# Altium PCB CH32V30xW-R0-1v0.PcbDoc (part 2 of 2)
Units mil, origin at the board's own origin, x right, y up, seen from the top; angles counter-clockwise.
Board outline 3543.31 x 3070.87 mil, 2 copper layers (Top Layer, Bottom Layer); 66 components, 88 nets, 346 pads, 719 vias.
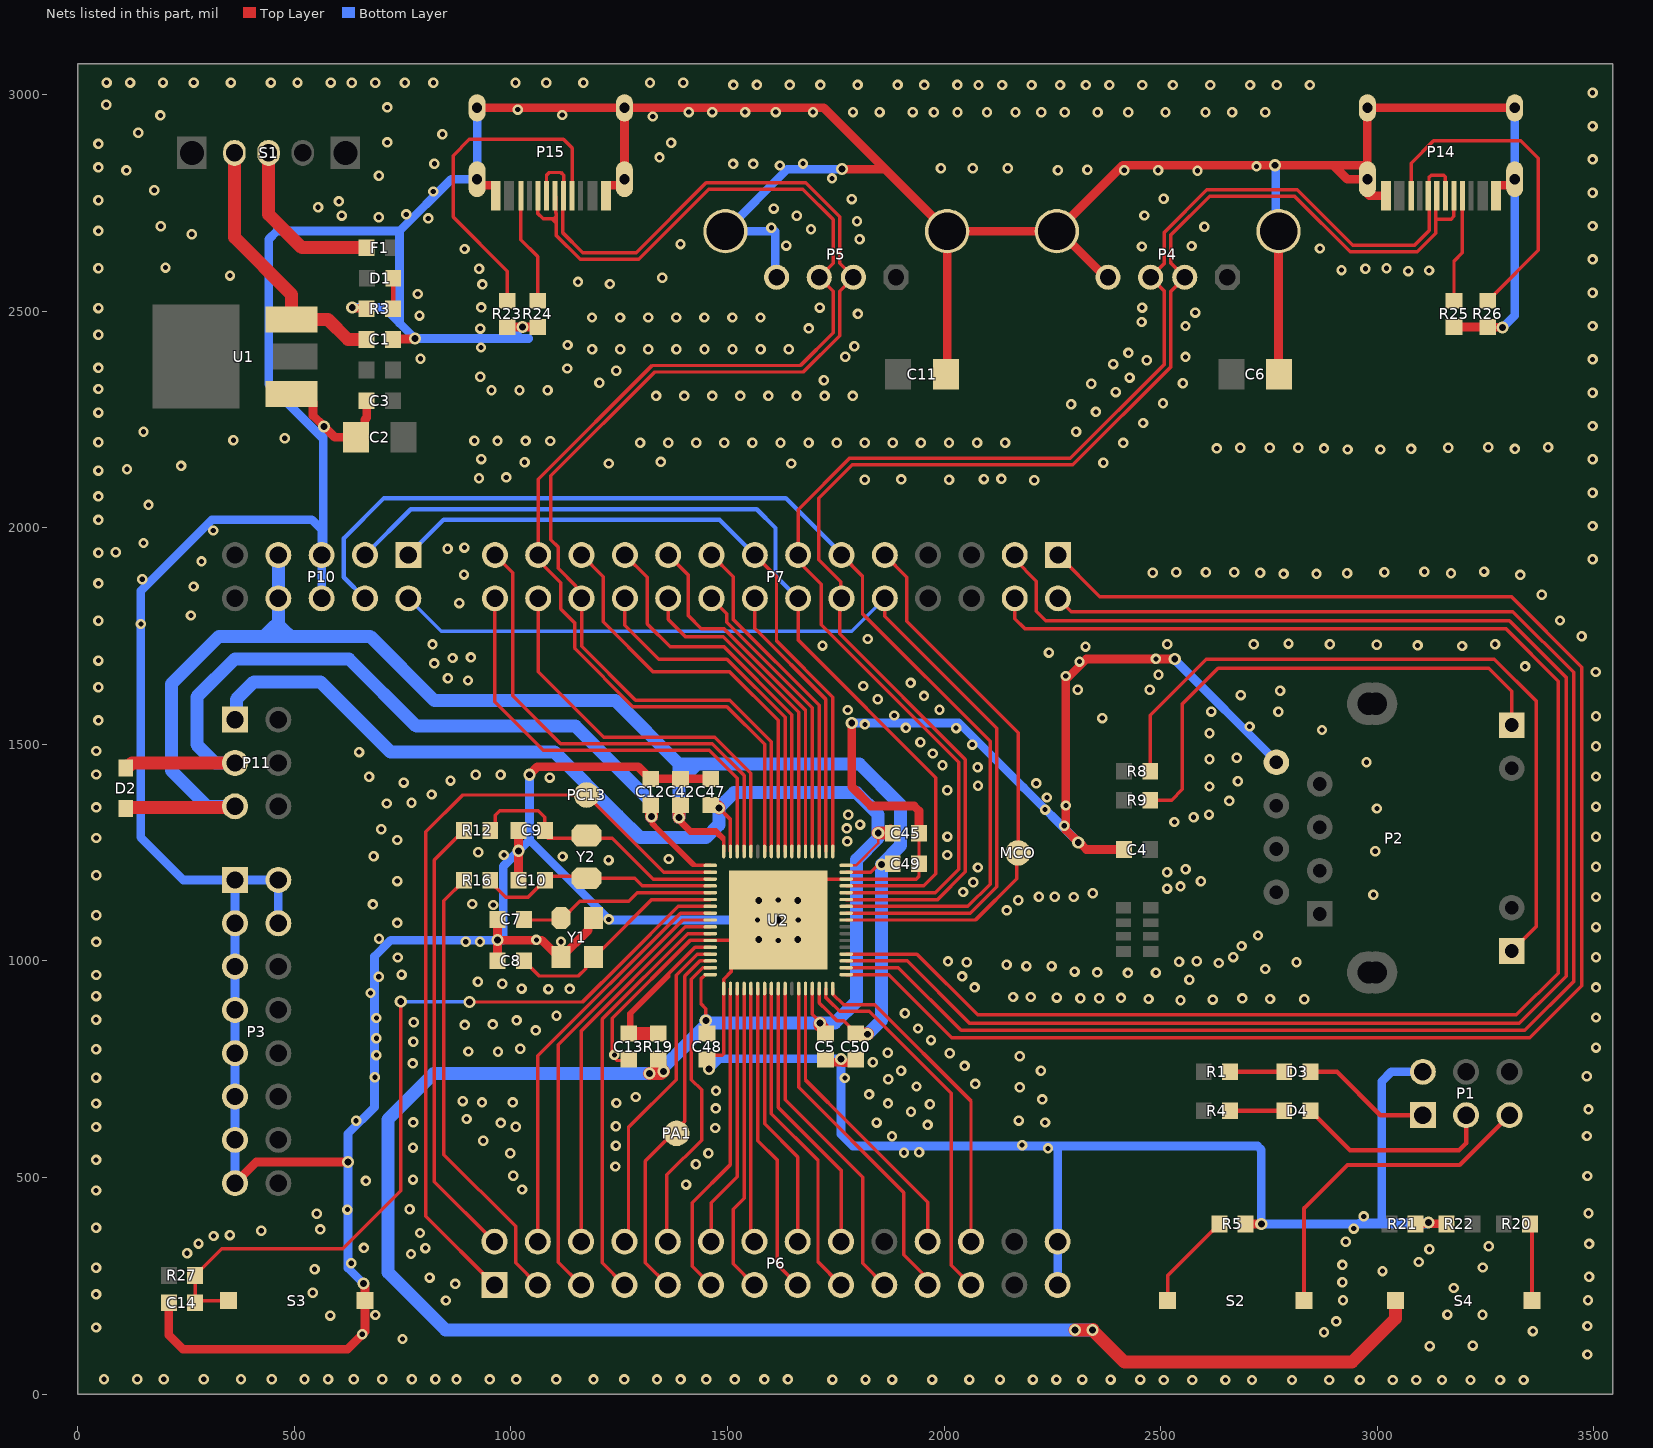
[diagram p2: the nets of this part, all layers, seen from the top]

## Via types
v1: diameter 24, hole 12, Top Layer to Bottom Layer, tented both sides, 662 vias
v2: diameter 28, hole 16, Top Layer to Bottom Layer, tented both sides, 57 vias

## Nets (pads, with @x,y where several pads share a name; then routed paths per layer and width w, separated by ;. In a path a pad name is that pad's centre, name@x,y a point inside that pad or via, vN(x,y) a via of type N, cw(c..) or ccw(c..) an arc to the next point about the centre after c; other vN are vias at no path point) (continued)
GND: C1.2 C2.2 C3.2 C4.1 C5.1 C6.2 C7.1 C8.1 C9.1 C10.1 C11.2 C12.1 C13.2 C14.1 C42.1 C45.2 C47.2 C48.2 C49.1 C50.2 P1.2 P2.8 P3.1 P3.2 P3.3 P3.4 P3.5 P3.7 P3.9 P3.11 P3.13 P3.15 P4.0 P4.4 P5.0 P5.4 P6.27 P6.28 P10.5 P10.6 P14.0 P14.A1 P14.B1 P15.0 P15.A1 P15.B1 R3.2 R5.1 R21.2 R22.2 R23.2 R24.2 R25.2 R26.2 S3.1 U1.1 U2.0 U2.12 U2.18 U2.49 Y1.2 Y1.4 | length 21484.4
  Top Layer w8: C13.2@1272.27,772.13 1270.31,770.17 1245.43,770.17 1234.02,781.57 1234.02,867.8 1413.47,1047.24 U2.12@1460.33,1047.24 U2.0@1569.86,1047.24 ; C48.2@1452.92,782.13 1487.61,782.13 1491.12,785.64 U2.18@1491.12,936.31 1491.12,957.77 1509.18,975.83 1509.18,986.56 U2.0@1569.86,1047.24 ; C45.2@1942.11,1294.49 C49.1@1942.11,1224.49 1942.11,1195.7 1935.38,1188.98 U2.49@1773.89,1188.98 1711.59,1188.98 U2.0@1662.12,1139.5 U2.0@1617.11,1094.49 U2.0@1572.09,1049.47 U2.0@1569.86,1047.24
  Top Layer w20: C14.1@210.37,211 210.37,136.41 243.22,103.56 622.7,103.56 663.07,143.93 S3.1@663.07,215.99 663.07,249.96 659.9,253.12 v2(659.9,255.29) ; P3.15@363.11,486.99 411.93,535.81 v2(624.09,535.81) ; U1.1@493.11,2309.25 523.11,2309.25 543.11,2289.25 543.11,2259.25 v2(568.33,2234.02) 593.56,2208.79 C2.2@642.33,2208.79 662.33,2228.79 662.33,2249.49 667.02,2254.18 C3.2@667.02,2293.47 ; v2(633.71,2508.57) 635.24,2507.04 665.35,2507.04 R3.2@667.02,2505.37 ; C1.2@727.65,2434.74 728.79,2435.87 777.31,2435.87 v2(778.45,2437.01) ; P15.0@921.95,2804.74 921.95,2799.95 930.9,2791 963.25,2791 965.06,2789.19 P15.B1@965.06,2766.56 ; P15.0@921.95,2969.31 P15.0@1262.11,2969.31 ; C8.1@969.2,1000.46 v2(969.2,1048.1) ; C7.1@969.2,1095.74 v2(969.2,1048.1) ; R23.2@991.75,2463.29 v2(1026.93,2463.29) R24.2@1062.11,2463.29 ; C10.1@1017.69,1193.12 v2(1017.69,1254.24) C9.1@1017.69,1283.12 ; v2(1042.76,1429.86) 1061.01,1448.12 1293.89,1448.12 1321.65,1420.35 C12.1@1322.64,1420.35 C42.1@1391.63,1420.35 C47.2@1461.63,1420.35 ; Y1.2@1115.58,1003.93 Y1.2@1115.58,1007.87 ; Y1.4@1190.39,1094.48 1178.73,1082.83 1178.73,1071.02 Y1.2@1115.58,1007.87 ; P15.A1@1219,2766.56 1219,2789.19 1220.81,2791 1253.16,2791 1262.11,2799.95 P15.0@1262.11,2804.74 P15.0@1262.11,2969.31 ; C48.2@1456.07,778.98 1456.07,751.9 v2(1457.6,750.37) ; C5.1@1726.06,772.13 1731.92,766.27 1761.87,766.27 v2@1761.87,769.2 ; v2(1761.87,774.01) v2@1761.87,769.2 ; v2(1764.46,2827.89) 1863.76,2827.89 P5.0@2007.11,2684.55 ; v2(1786.84,1549.38) 1786.84,1401.91 1831.17,1357.59 1930.74,1357.59 1942.11,1346.23 C45.2@1942.11,1294.49 ; C50.2@1796.06,772.13 1789.06,765.13 1765.94,765.13 v2@1761.87,769.2 ; C11.2@2004,2354.26 2007.11,2357.37 P5.0@2007.11,2684.55 ; P5.0@2037.11,2684.55 P4.0@2260.3,2684.55 ; P4.0@2300.3,2684.55 P4.0@2266.2,2684.55 ; P4.4@2378.41,2578.25 2372.5,2578.25 P4.0@2266.2,2684.55 ; C4.1@2415.29,1257.18 2328.53,1257.18 2311.92,1273.79 v2(2309.76,1273.79) 2281.19,1302.35 2281.19,1649.69 2328.49,1696.98 v2(2532.5,1696.98) ; R5.1@2696,392.95 2696.1,392.85 2732.18,392.85 v2(2732.28,392.75) ; P4.0@2772.11,2684.55 2772.11,2355.15 C6.2@2773,2354.26 ; P14.0@2968.44,2836.82 2898.44,2836.82 ; P14.0@2968.83,2804.07 2968.16,2804.74 2930.51,2804.74 2898.44,2836.82 ; P14.B1@3020.22,2766.56 2982.18,2766.56 2968.83,2779.9 2968.83,2796.47 P14.0@2977.11,2804.74 P14.0@2977.11,2969.31 P14.0@3317.26,2969.31 ; v2(3118.11,395.96) 3116.61,394.45 3090.13,394.45 R21.2@3088.63,392.95 R22.2@3159.37,392.95 ; R25.2@3177.11,2463.25 R26.2@3255.21,2463.25 3255.91,2462.55 3288.54,2462.55 v2(3289.24,2461.85) ; P14.A1@3274.15,2766.56 3274.15,2789.19 3275.96,2791 3308.32,2791 3317.26,2799.95 P14.0@3317.26,2804.74 ; v2(969.2,1048.1) 1071.41,1048.1 1099.99,1019.52 1103.93,1019.52 Y1.2@1115.58,1007.87 ; P15.0@1262.11,2969.31 1722.34,2969.31 P5.0@2007.11,2684.55 ; P4.0@2260.3,2684.55 P4.0@2266.2,2684.55 ; P4.0@2260.3,2684.55 2412.57,2836.82 v2(2764.24,2836.82) 2898.44,2836.82
  Bottom Layer w20: P3.15@363.11,486.99 P3.13@363.11,586.99 P3.11@363.11,686.99 P3.9@363.11,786.99 P3.7@363.11,886.99 P3.5@363.11,986.99 P3.3@363.11,1086.99 P3.1@363.11,1186.99 ; P3.4@463.11,1086.99 P3.2@463.11,1186.99 P3.1@363.11,1186.99 ; P10.6@563.11,1836.99 P10.5@563.11,1936.99 ; v2(568.33,2234.02) 566.8,2232.49 566.8,2205.35 ; v2(633.71,2508.57) 706.89,2508.57 742.67,2472.79 ; v2(659.9,255.29) 624.09,291.1 v2(624.09,535.81) 624.09,601.43 685.07,662.41 685.07,1010.31 722.86,1048.1 v2(969.2,1048.1) ; P15.0@921.95,2969.31 P15.0@921.95,2804.74 862.36,2804.74 742.67,2685.06 ; v2@982.2,1048.1 982.2,1218.76 v2(1017.69,1254.24) 1042.76,1279.31 ; v2(1026.93,2463.29) 1000.65,2437.01 ; 1040.65,2437.01 1000.65,2437.01 ; v2(1042.76,1429.86) 1042.76,1279.31 ; v2(1457.6,750.37) 1481.23,774.01 1761.85,774.01 1761.85,600.12 1789.22,572.75 2262.11,572.75 ; v1(1569.11,1094.49) 1227.58,1094.49 1042.76,1279.31 ; P5.4@1613.41,2578.25 1610.39,2581.26 1610.39,2684.55 P5.0@1495.3,2684.55 1638.64,2827.89 v2(1764.46,2827.89) ; v2(1786.84,1549.38) 2034.17,1549.38 2183.35,1400.19 v2(2309.76,1273.79) ; P6.27@2262.11,251.99 2262.11,572.75 ; v2(2532.5,1696.98) 2532.5,1695.04 2767.11,1460.43 P2.8@2767.11,1458.49 ; v2(2764.24,2836.82) 2765.77,2835.29 2765.77,2690.88 P4.0@2772.11,2684.55 ; 2959.96,395.96 3010.1,395.96 ; P1.2@3105.11,743.99 3032.36,743.99 3010.1,721.73 3010.1,395.96 ; v2(3118.11,395.96) v2@3115.94,395.96 ; v2(3289.24,2461.85) 3317.26,2489.88 P14.0@3317.26,2804.74 P14.0@3317.26,2969.31 ; P3.1@363.11,1186.99 243.46,1186.99 145.3,1285.15 145.3,1853.97 309.78,2018.45 540.61,2018.45 563.11,1995.95 P10.5@563.11,1936.99 ; P10.5@563.11,1936.99 566.8,1940.69 566.8,2205.35 ; 566.8,2205.35 441.19,2330.97 441.19,2666.23 460.01,2685.06 742.67,2685.06 ; 742.67,2472.79 v2(778.45,2437.01) 1000.65,2437.01 ; 742.67,2472.79 742.67,2685.06 ; 2262.11,572.75 2723.49,572.75 2732.28,563.96 v2(2732.28,392.75) 2959.96,392.75 3010.1,392.75 3112.74,392.75 v2@3115.94,395.96 ; 3010.1,395.96 v2@3115.94,395.96
  other v1: 2507.06,32.56 2572.8,32.56 2649.39,32.56 2710.83,32.56 2803.11,32.56 2889.07,32.56 2959.85,32.56 3035.7,32.56 3090.05,32.56 3149.46,32.56 3215.19,32.56 3283.45,32.56 3337.81,32.56 60.73,34.18 137.31,34.18 198.76,34.18 291.04,34.18 376.99,34.18 447.78,34.18 523.62,34.18 577.98,34.18 637.39,34.18 703.12,34.18 771.38,34.18 825.73,34.18 874.47,34.03 951.06,34.03 1012.5,34.03 1104.78,34.03 1190.73,34.03 1261.52,34.03 1337.37,34.03 1391.72,34.03 1451.13,34.03 1516.86,34.03 1585.12,34.03 1639.48,34.03 1742.05,33.56 1818.64,33.56 1880.08,33.56 1972.36,33.56 2058.32,33.56 2129.1,33.56 2204.95,33.56 2259.3,33.56 2318.71,33.56 2384.44,33.56 2452.7,33.56 3485.11,91.46 3120.94,110.98 3220.32,112.03 749.84,127.14 656.69,138.27 2876.95,143.05 3359.13,145.48 42.47,153.73 3485.11,157.2 2905.28,167.8 583,181.37 687.27,182.76 3242.93,183.02 3161.95,183.54 849.95,216.13 2920.83,216.77 3486.37,216.61 42.47,230.32 542.68,234.2 3176.68,245.07 871.57,254.51 2919.44,258.38 812.41,268.96 3488.9,270.96 3012.09,283.98 546.85,288.42 42.47,291.77 3243.46,292.39 2919.44,298.38 631.66,302.33 3095.7,305.01 769.45,323.53 252.63,325 3120.41,334.46 802.67,337.09 660.66,337.64 3257.13,341.29 278.74,347.48 3488.9,346.81 2927.06,351.7 313.74,365.07 351.27,367.07 790.16,371.85 423.81,377.22 560.1,380.17 2945.63,382.18 42.47,384.04 2968.96,410.27 551.78,416.22 3487.64,417.59 622.48,425.92 766.12,426.93 42.47,470 1025.93,472.46 1404.45,483.73 665.34,492.21 773.93,495.13 1005.24,504 3485.11,503.55 1241.27,525.51 1427.14,530.62 42.47,540.79 998.34,556.23 1455.88,555.83 1907.45,557.12 1942.29,558.3 2239.77,567.36 773.93,569.01 1242.31,573.74 2180.06,574.96 936.25,584.81 1879.69,595.5 3483.85,595.83 1471.51,614.31 42.47,616.63 1011.15,617.34 1242.31,618.21 1961.94,621.46 976.66,626.21 774.64,627.26 1844.26,626.8 2233.25,627.07 642.7,631.17 2172.47,631.41 897.81,635.08 1923.64,651.7 3487.53,657.27 1473.02,659.69 1967.32,669.17 42.47,670.98 1870.55,671.19 1243.64,671.97 933.29,673.51 1004.25,673.51 888.94,676.47 2226.74,680.26 1288.1,685.9 1826.87,692.02 1473.52,700.02 2174.64,708.48 1936.41,710.16 2071.76,716.08 1871.14,726.69 42.47,730.4 1771.1,729.65 686.15,731.32 3483.7,733.86 1900.79,746.45 2223.48,746.47 2047.3,757.68 773.32,763.58 1835.61,765.94 2174.64,780.12 689.58,782.72 1238.98,782.99 2013.04,787.04 1869.88,788.12 970.25,790.16 901.85,791 42.47,796.13 1021.44,797.29 3504.96,799.93 774.89,813.31 1969.82,817.21 689.58,821.55 1057.53,839.67 1939.64,844.13 893.46,852.26 958.08,853.52 775.52,858.64 1013.05,862.75 42.47,864.39 689.58,868.38 3504.96,869.48 1105.36,873.24 1909.47,879.2 2545.81,909.24 2620.32,910.65 2831.19,911.35 2472,912.05 2752.47,912.05 2688.5,913.46 2314.68,913.91 2358.04,913.91 2260.13,915.31 2408.4,914.61 2159.41,916.71 2199.98,916.71 42.47,918.74 675.83,926.05 1086.47,934.99 1136.07,935.47 1024.75,936.04 2070.38,939.01 3504.96,939.03 979.85,947.27 923.72,951.95 2566.29,956.65 694.85,963.46 2041.51,964.41 42.62,967.48 747.6,968.37 2424.36,972.5 2489.03,973.08 2353.33,973.65 2301.36,975.39 2741.38,981.44 2189.91,988.09 2248.24,988.09 2144.3,990.98 2633.91,995.35 2052.48,996.75 2813.44,996.93 2542.42,998.19 2008.97,998.85 2583.2,999.25 739.01,1007.98 2667.6,1008.83 3504.96,1008.57 2686.75,1034.36 42.62,1044.06 895.92,1044.42 928.6,1044.07 1115.58,1044.52 1617.11,1047.49 1058.83,1048.63 695.46,1051.17 2724.7,1058.83 3504.96,1078.12 737.5,1087.84 1663.11,1094.49 1226.04,1095.99 42.62,1105.51 2144.5,1116.72 959.11,1129.03 681.47,1130.44 910.72,1131.34 1617.11,1140.49 2171.18,1140.31 2218.89,1148.01 2255.32,1148.01 2299.44,1147.5 3504.96,1147.66 2991.1,1152.58 2343.04,1156.22 2043.9,1159.02 2514.9,1166.99 2545.69,1172.12 2067.17,1181.56 737.5,1184.26 2592.88,1183.92 42.62,1197.78 2514.9,1204.96 2557.48,1211.62 2077.93,1215.74 3504.96,1217.21 1225.42,1232.86 1364.48,1235.22 683.1,1241.47 1119.26,1241.02 983.73,1244.64 2007.07,1244.57 924.63,1251.06 2995.12,1253.25 1776.28,1275.89 737.5,1279.18 42.62,1283.74 2007.55,1287.06 3504.96,1286.76 700.92,1304.09 1775.49,1306.02 2277.53,1312.16 1806.04,1314.73 2531.69,1320.78 2576.07,1331.7 1778.55,1337.26 2611.58,1337.85 2233.14,1349.27 2999.15,1351.91 42.62,1354.53 3504.96,1356.3 2281.16,1358.73 713.4,1363.55 770.65,1365.06 2658.19,1369.5 2237.34,1377.35 816.86,1384.18 2007.07,1394.02 2612.73,1402.63 2078.28,1404.24 2212.65,1409.91 752.57,1411.76 2678.3,1414.75 860.51,1416.21 1089.61,1423.11 672.72,1425.32 3504.96,1425.85 42.62,1430.37 918.74,1430 976.21,1430 2077.28,1447.1 1996.32,1451.62 2974.99,1458.63 2612.73,1465.62 2675.79,1469.21 1973.86,1478.84 649.53,1482.19 42.62,1484.73 3504.96,1495.39 2065,1499.34 1945.27,1504.71 2612.73,1525.6 2872.3,1533.13 2027.64,1537.38 1911.75,1538.07 2705.17,1541.19 1817.19,1546.01 47.7,1555.19 2365.3,1560.68 3504.96,1564.94 1884.85,1566.57 2771.62,1575.42 2616.73,1575.59 1777.72,1579.31 1989.32,1580.07 1846.66,1603.98 1953.63,1611.8 2685.04,1613.67 2775.65,1623.74 2308.47,1625.84 2474.82,1625.84 47.7,1631.77 1813.22,1634.68 1922.7,1641.94 900.9,1647.33 854.6,1652.52 2280.74,1657.72 2494.98,1660.58 3504.2,1667.06 3341.26,1679.9 823.07,1686.84 2312.62,1690.99 47.7,1693.22 2488.96,1697.24 865.38,1699.22 907.68,1700.81 2241.92,1711.79 2326.49,1725.65 3195.7,1727.04 1719.4,1727.89 3093.12,1728.42 2998.85,1729.81 819.08,1730.75 2515.03,1731.2 2714.65,1731.2 2890.71,1731.2 3271.95,1731.2 2795.06,1732.58 1823.72,1743.12 3471.65,1749.4 145.78,1777.76 47.7,1785.5 3421.87,1785.77 261.34,1797.53 880.95,1825.96 3379.74,1845.13 267.43,1864.44 47.7,1871.45 148.82,1881.16 3329.96,1891.08 891.78,1891.82 2783.78,1893.54 2859.62,1893.54 2930.41,1894.8 3170.09,1894.91 2481.67,1896.07 2729.42,1896.07 2536.02,1897.33 2604.28,1897.33 2670.01,1897.33 3016.37,1897.33 3108.64,1898.6 3246.68,1898.74 285.67,1922.22 3496.95,1927.08 47.7,1942.24 87.99,1943.51 853.89,1951.36 892.68,1954.07 151.86,1964.8 313.04,1993.69 3496.95,2004.02 47.7,2018.08 163.38,2052.8 47.7,2072.44 3496.95,2080.95 2208,2109.71 1817.04,2110.74 2011.51,2110.74 1901,2111.58 2091.92,2112.34 2132.37,2112.86 926.43,2114.17 989.28,2116.23 47.7,2131.85 113.84,2135.1 238.55,2142.79 1225.66,2148.22 1647.11,2148.22 2367.81,2150.02 1031.52,2151.27 1345.89,2152.01 931.58,2158.48 3496.95,2157.89 2931.38,2180.69 3007.22,2180.69 3078.01,2181.95 3317.69,2182.06 2629.27,2183.22 2877.02,2183.22 2683.62,2184.48 2751.88,2184.48 2817.61,2184.48 3163.97,2184.48 3256.24,2185.75 3394.28,2185.89 1298.19,2196.22 1363.02,2196.22 1427.85,2196.22 1492.67,2196.22 1557.5,2196.22 1622.32,2196.22 1687.15,2196.22 1751.97,2196.22 1816.8,2196.22 1881.63,2196.22 1946.45,2196.22 2011.28,2196.22 2076.1,2196.22 2140.93,2196.22 2413.65,2195.85 47.7,2197.58 1090.61,2200.27 915.74,2200.69 969.02,2200.58 1033.85,2200.58 359.29,2202.02 477.75,2206.57 151.86,2221.78 2304.69,2221.54 3496.95,2234.83 2459.49,2241.69 47.7,2265.84 2350.53,2267.38 2293.14,2285.07 2505.32,2287.53 1335.14,2304.3 1399.97,2304.3 1464.79,2304.3 1529.62,2304.3 1594.44,2304.3 1659.27,2304.3 1724.1,2304.3 1788.92,2304.3 3496.95,2311.77 2396.37,2313.22 955.1,2317.45 1019.92,2317.45 1084.75,2317.45 47.7,2320.19 2339.73,2332.24 2551.16,2333.37 1204.34,2334.67 1722.46,2340.28 2428.31,2346.62 929.22,2348.4 1243.24,2362.33 1130,2367.51 47.86,2368.93 2390.35,2377.68 2468,2386.88 3496.95,2388.71 791.39,2389.95 2557.16,2394.36 1771.92,2394.83 2425.43,2403.56 1187.49,2412.17 1252.31,2412.17 1317.14,2412.17 1381.96,2412.17 1446.79,2412.17 1511.62,2412.17 1576.44,2412.17 1641.27,2412.17 931.01,2416.13 1793.01,2418.83 1130.86,2421.97 47.86,2445.52 929.34,2459.72 1687.56,2460.28 2557.16,2465.69 3496.95,2465.65 2455.92,2474.89 1187.26,2485.28 1252.09,2485.28 1316.91,2485.28 1381.74,2485.28 1446.56,2485.28 1511.39,2485.28 1576.22,2485.28 788.89,2489.68 1801.01,2493.74 2579.73,2496.58 47.86,2506.96 1713.01,2508.28 2457.07,2508.25 931.44,2508.59 785.15,2539.55 3496.95,2542.59 934.23,2561.66 1228.52,2562.6 1154.92,2567.41 1349.59,2577.04 351.67,2582.07 3071.71,2592.5 3119.64,2593.82 2917.38,2594.77 926.57,2597.83 2972.57,2598.1 47.86,2599.24 3021.31,2598.96 202.63,2600.47 3496.95,2619.53 893.03,2643.36 2867.46,2644.69 2456.69,2649.23 2571.29,2650.37 1635.74,2651.33 1391.55,2654.77 1805.05,2665.78 263.35,2677.75 47.86,2685.19 1692.83,2689.17 1601.35,2692.61 2600.8,2694.62 191.59,2696.14 3496.95,2696.47 1798.97,2707.6 809.39,2714.01 695.08,2716.8 1659.82,2720.12 609.57,2720.52 2462.36,2720.72 758.27,2723.31 1606.85,2736.63 554.86,2739.98 603.01,2753.29 47.86,2755.98 1786.8,2758.55 2506.61,2759.3 3496.95,2773.4 820.54,2776.28 176.87,2778.94 1741.17,2806.46 695.2,2812.71 2584.91,2823.98 112.48,2824.94 2262.65,2825.11 2415.84,2825.11 2494.13,2825.11 2330.73,2826.25 1992.59,2829.65 2066.34,2829.65 2146.91,2829.65 47.86,2831.83 2721.08,2834.19 1621.02,2836.12 823.33,2840.41 1513.04,2839.92 1559.43,2839.92 1674.26,2840.68 3496.95,2850.34 1342.95,2854.99 47.86,2886.18 1369.88,2888.65 714.66,2889.53 841.92,2908.26 139.68,2911.7 3496.95,2927.28 1327.24,2949.25 190.99,2951.86 1118.51,2952.85 1410.53,2959.48 1464.89,2959.48 1540.73,2959.48 1611.52,2959.48 1697.48,2959.48 1789.75,2959.48 1851.2,2959.48 1927.78,2959.48 1976.52,2959.32 2030.87,2959.32 2099.13,2959.32 2164.87,2959.32 2224.28,2959.32 2278.63,2959.32 2354.47,2959.32 2425.26,2959.32 2511.22,2959.32 2603.5,2959.32 2664.94,2959.32 2741.53,2959.32 1015.64,2965.24 714.66,2970.46 66.07,2976.4 3496.95,3004.22 1513.51,3022.31 1567.86,3022.31 1643.7,3022.31 1714.49,3022.31 1800.45,3022.31 1892.72,3022.31 1954.17,3022.31 2030.76,3022.31 2079.49,3022.15 2133.85,3022.15 2202.11,3022.15 2267.84,3022.15 2327.25,3022.15 2381.6,3022.15 2457.45,3022.15 2528.23,3022.15 2614.19,3022.15 2706.47,3022.15 2767.91,3022.15 2844.5,3022.15 632.66,3027.39 687.02,3027.39 755.28,3027.39 821.01,3027.39 1010.62,3027.39 1081.4,3027.39 1167.36,3027.39 1321.08,3027.39 1397.67,3027.39 66.68,3027.54 121.03,3027.54 196.87,3027.54 267.66,3027.54 353.62,3027.54 445.89,3027.54 507.34,3027.54 583.93,3027.54
KEY: P1.5 S2.1 | length 776.3
  Top Layer w10: S2.1@2830.75,215.99 2830.75,428.73 2931.07,529.05 3190.16,529.05 P1.5@3305.11,643.99
LED1: D3.2 P1.1 | length 300.8
  Top Layer w10: D3.2@2845.74,743.99 2907.08,743.99 3007.08,643.99 P1.1@3105.11,643.99
LED2: D4.2 P1.3 | length 469.3
  Top Layer w10: D4.2@2845.74,653.99 2845.74,653 2859.04,639.7 2860.03,639.7 2936.97,562.75 3188.6,562.75 3205.04,579.19 3205.04,643.92 P1.3@3205.11,643.99
MCO: MCO.1 P7.9 U2.43 | length 1308.1
  Top Layer w8: U2.43@1773.89,1094.49 2072.5,1094.49 2167.96,1189.95 MCO.1@2167.96,1249.31 ; P7.9@1863.11,1936.99 1914.04,1886.05 1914.04,1783.72 2170.88,1526.89 MCO.1@2170.88,1249.31
NetC1_1: C1.1 S1.2 U1.3 | length 631.7
  Top Layer w30: S1.2@361.84,2865.37 361.84,2670.28 493.11,2539.01 U1.3@493.11,2481.25 577.27,2481.25 623.79,2434.74 C1.1@667.02,2434.74
NetD1_2: D1.2 R3.1 | length 70.9
  Top Layer w10: R3.1@727.65,2505.37 728.34,2506.06 D1.2@728.34,2576.01
NetD3_1: D3.1 R1.2 | length 125
  Top Layer w10: R1.2@2660.11,743.99 D3.1@2785.11,743.99
NetD4_1: D4.1 R4.2 | length 125
  Top Layer w10: R4.2@2660.11,653.99 D4.1@2785.11,653.99
NetF1_2: F1.2 S1.1 | length 400.1
  Top Layer w30: S1.1@440.58,2865.37 440.58,2723.61 517.54,2646.64 F1.2@667.02,2646.64
NetP2_9: P2.9 R8.2 | length 1714.5
  Top Layer w8: R8.2@2475.92,1437.8 2475.92,1566.82 2605.47,1696.37 3270.22,1696.37 3367.43,1599.15 3367.43,1080.2 P2.9@3310.1,1022.86
NetP2_12: P2.12 R9.2 | length 1175.7
  Top Layer w8: R9.2@2475.92,1371.1 2525.16,1371.1 2550.19,1396.13 2550.19,1593.2 2632.28,1675.3 3257.63,1675.3 3310.1,1622.83 P2.12@3310.1,1544.52
NetP14_A5: P14.A5 R25.1 | length 250.7
  Top Layer w8: R25.1@3177.11,2523.88 3177.11,2615.23 3196.4,2634.52 P14.A5@3196.4,2766.56
NetP14_B5: P14.B5 R26.1 | length 784.8
  Top Layer w8: P14.B5@3078.29,2766.56 3078.29,2841.75 3129.85,2893.31 3331.37,2893.31 3371.97,2852.71 3371.97,2640.65 3270.5,2539.17 3270.5,2538.19 3256.19,2523.88 R26.1@3255.21,2523.88
NetP15_A5: P15.A5 R23.1 | length 795.6
  Top Layer w8: R23.1@991.75,2523.92 991.75,2592.05 866.48,2717.32 866.48,2859.12 903.81,2896.45 1121.38,2896.45 1141.24,2876.58 P15.A5@1141.24,2766.56
NetP15_B5: P15.B5 R24.1 | length 258.8
  Top Layer w8: P15.B5@1023.13,2766.56 1023.13,2665.15 1062.11,2626.17 R24.1@1062.11,2523.92
NetR5_2: R5.2 S2.2 | length 227.1
  Top Layer w8: S2.2@2515.79,215.99 2515.79,273.37 2620.08,377.66 2621.06,377.66 2635.37,391.96 R5.2@2635.37,392.95
NetR20_2: R20.2 S4.2 | length 178.8
  Top Layer w10: R20.2@3352.49,392.95 3356.96,388.48 S4.2@3356.96,215.99
NRST: C14.2 R27.1 S3.2 U2.7 | length 1942
  Top Layer w8: S3.2@348.11,215.99 275.99,215.99 C14.2@271,211 R27.1@271,274 271,274.98 285.31,289.29 286.29,289.29 332.57,335.57 611.38,335.57 745.76,469.95 v2(745.76,906.68) ; v2(904.17,905.2) 1165.36,905.2 1258.66,998.5 1386.14,1125.98 U2.7@1460.33,1125.98
  Bottom Layer w8: v2(745.76,906.68) 746.5,905.94 903.43,905.94 v2(904.17,905.2)
PA0: P6.8 U2.14 | length 763.4
  Top Layer w8: P6.8@1262.11,351.99 1271.5,361.38 1271.5,615.83 1381.5,725.83 1381.5,966.78 1430.46,1015.75 U2.14@1460.33,1015.75
PA1: P6.9 PA1.1 U2.15 | length 845.4
  Top Layer w8: P6.9@1362.11,251.99 1310.47,303.62 1310.47,538.2 1401.73,629.46 1401.73,965.15 1436.58,1000 U2.15@1460.33,1000
PA2: P6.10 U2.16 | length 704.4
  Top Layer w8: P6.10@1360.15,350.87 1360.15,505.98 1440.25,586.08 1440.25,702.51 1416.73,726.03 1416.73,957.85 1443.08,984.19 1460.26,984.19 U2.16@1460.33,984.25
PA3: P6.11 U2.19 | length 738.8
  Top Layer w8: P6.11@1462.11,251.99 1418.74,295.35 1418.74,442.06 1506.87,530.19 U2.19@1506.87,936.31
PA4: P6.12 U2.20 | length 609.4
  Top Layer w8: P6.12@1462.11,351.99 1462.11,441.56 1522.62,502.08 U2.20@1522.62,936.31
PA5: P6.13 U2.21 | length 715
  Top Layer w8: U2.21@1538.37,936.31 1538.37,452.22 1513.15,427.01 1513.15,300.95 P6.13@1562.11,251.99
PA6: P6.14 U2.22 | length 587.6
  Top Layer w8: U2.22@1554.11,936.31 1554.18,936.24 1554.18,359.92 P6.14@1562.11,351.99
PA7: P6.15 U2.23 | length 722.5
  Top Layer w8: U2.23@1569.86,936.31 1569.86,585.1 1615.35,539.61 1615.35,298.74 P6.15@1662.11,251.99
PA9: P7.10 P10.2 U2.44 | length 2308.7
  Top Layer w8: U2.44@1773.89,1110.24 2060.39,1110.24 2121.3,1171.15 2121.3,1537.51 1863.11,1795.7 P7.10@1863.11,1836.99
  Bottom Layer w8: P10.2@763.11,1836.99 839.48,1760.61 1786.73,1760.61 P7.10@1863.11,1836.99
PA10: P7.11 P10.4 U2.45 | length 2657.7
  Top Layer w8: P7.11@1763.11,1936.99 1811.65,1888.44 1811.65,1801.76 2106.3,1507.11 2106.3,1177.36 2054.93,1125.98 U2.45@1773.89,1125.98
  Bottom Layer w10: P10.4@663.11,1836.99 614.17,1885.93 614.17,1975.39 707.23,2068.46 1634.38,2068.46 1763.11,1939.73 P7.11@1763.11,1936.99
PA11: P4.2 P7.12 P14.A7 P14.B7 U2.46 | length 3476.6
  Top Layer w8: U2.46@1773.89,1141.73 1985.22,1141.73 2049.07,1205.58 2049.07,1464.93 1758.92,1755.07 1758.92,1832.8 P7.12@1763.11,1836.99 1761.88,1838.22 1761.88,1874.99 1710.37,1926.5 1710.37,2067.66 1787.74,2145.03 2297.34,2145.03 2523.7,2371.39 2523.7,2546.38 P4.2@2555.57,2578.25 2523.7,2610.12 2523.7,2676.18 2612.99,2765.47 2808.98,2765.47 2937.21,2637.24 3092.22,2637.24 3135,2680.02 3135,2712.31 ; P14.A7@3137.34,2766.56 3135.44,2764.65 3135.44,2727.01 3135,2726.57 3135,2712.31 ; P14.B7@3176.71,2766.56 3176.71,2718.74 3170.28,2712.31 3143.56,2712.31 3140.1,2712.31 3135,2712.31
PA12: P4.3 P7.13 P14.A6 P14.B6 U2.47 | length 3509.4
  Top Layer w8: U2.47@1773.89,1157.48 1785.57,1157.48 1785.95,1157.11 1979.38,1157.11 2034.07,1211.79 2034.07,1458.71 1716.87,1775.9 1716.87,1788.52 1716.37,1789.02 1716.37,1869.3 1676.77,1908.91 1676.77,1909.26 1663.11,1922.92 1663.11,2041.61 1781.52,2160.03 2291.13,2160.03 2508.7,2377.6 2508.7,2546.38 P4.3@2476.83,2578.25 2508.7,2610.12 2508.7,2682.39 2606.78,2780.47 2815.2,2780.47 2943.43,2652.24 3086.01,2652.24 3120,2686.23 3120,2726.57 3119.56,2727.01 3119.56,2764.65 3119.42,2764.79 3119.42,2809 3124.25,2813.84 3153.51,2813.84 3157.03,2810.32 P14.A6@3157.03,2766.56
PA13: P7.14 P10.3 U2.48 | length 2179.4
  Top Layer w8: P7.14@1663.11,1836.99 1663.11,1740.77 1980.75,1423.13 1980.75,1201.2 1952.77,1173.23 U2.48@1773.89,1173.23
  Bottom Layer w10: P10.3@663.11,1936.99 768.84,2042.73 1567.54,2042.73 1610.96,1999.31 1610.96,1889.14 P7.14@1663.11,1836.99
PA14: P7.15 P10.1 U2.52 | length 1626.5
  Top Layer w8: P7.15@1563.11,1936.99 1613.14,1886.96 1613.14,1738.89 1743.09,1608.94 U2.52@1743.09,1252.67
  Bottom Layer w10: P10.1@763.11,1936.99 844.72,2018.61 1481.49,2018.61 P7.15@1563.11,1936.99
PA15: P7.16 U2.53 | length 652.3
  Top Layer w8: P7.16@1563.11,1836.99 1563.11,1767.71 1727.34,1603.48 U2.53@1727.34,1252.67
PB0: P6.18 U2.26 | length 644.4
  Top Layer w8: U2.26@1617.11,936.31 1617.11,661.71 1762.11,516.71 P6.18@1762.11,351.99
PB1: P6.19 U2.27 | length 779.3
  Top Layer w8: U2.27@1632.85,936.31 1632.85,679.74 1811.97,500.63 1811.97,302.13 P6.19@1862.11,251.99
PB3: P7.21 U2.58 | length 916.9
  Top Layer w8: P7.21@1263.11,1936.99 1314.58,1885.52 1314.58,1777.86 1367.6,1724.83 1492,1724.83 1648.6,1568.23 U2.58@1648.6,1252.67
PB4: P7.22 U2.59 | length 829.7
  Top Layer w8: P7.22@1263.11,1836.99 1263.11,1775.15 1341.48,1696.78 1498.84,1696.78 1632.85,1562.77 U2.59@1632.85,1252.67
PB5: P7.23 U2.60 | length 975.8
  Top Layer w8: P7.23@1163.11,1936.99 1213.03,1887.07 1213.03,1783.1 1329.05,1667.08 1505.54,1667.08 1617.11,1555.52 U2.60@1617.11,1252.67
PB6: P5.2 P7.24 P15.A7 P15.B7 U2.61 | length 3290.1
  Top Layer w8: P15.A7@1082.18,2766.56 1082.18,2814.09 1088.16,2820.07 1115.54,2820.07 1121.56,2814.06 P15.B7@1121.56,2766.56 1119.65,2764.65 1119.65,2727.01 1119.21,2726.57 1119.21,2713.28 1119.21,2681.53 1165.97,2634.77 1288.95,2634.77 1450.37,2796.18 1680.19,2796.18 1758.7,2717.68 1758.7,2610.12 P5.2@1790.57,2578.25 1758.7,2546.38 1758.7,2443.56 1674.7,2359.56 1331.95,2359.56 1092.18,2119.79 1092.18,1972.66 1109.26,1955.58 1109.26,1906.13 1149.88,1865.51 1149.88,1864.28 1163.11,1851.06 1163.11,1726.61 1287.69,1602.03 1505.01,1602.03 1600.98,1506.05 1600.98,1264.73 1601.36,1264.35 U2.61@1601.36,1252.67
PB7: P5.3 P7.25 P15.A6 P15.B6 U2.62 | length 3258.5
  Top Layer w8: P15.B6@1062.5,2766.56 1062.5,2725.11 1074.33,2713.28 1094.91,2713.28 ; P7.25@1063.11,1925.03 1115.05,1873.08 1115.05,1812.39 1146.91,1780.54 1146.91,1722.42 1148.11,1721.22 1148.11,1720.4 1281.48,1587.03 1498.79,1587.03 1585.98,1499.84 1585.98,1264.73 1585.61,1264.35 U2.62@1585.61,1252.67 ; P7.25@1063.11,1936.99 1062.97,1937.12 1062.97,2111.8 1325.74,2374.56 1668.48,2374.56 1743.7,2449.78 1743.7,2546.38 P5.3@1711.83,2578.25 1743.7,2610.12 1743.7,2711.46 1673.98,2781.18 1456.58,2781.18 1295.17,2619.77 1159.76,2619.77 1104.21,2675.32 1104.21,2704.22 1104.21,2713.28 ; P15.A6@1101.87,2766.56 1103.78,2764.65 1103.78,2727.01 1104.21,2726.57 1104.21,2718.28 1104.21,2713.28 ; 1103.36,2718.28 1098.36,2713.28 ; 1103.97,2704.22 1094.91,2713.28 ; 1094.91,2713.28 1098.36,2713.28 ; 1098.36,2713.28 1104.21,2713.28
PB8: P7.26 U2.64 | length 938.1
  Top Layer w8: P7.26@1063.11,1836.99 1063.11,1667.85 1214.18,1516.78 1470.87,1516.78 1554.11,1433.54 U2.64@1554.11,1252.67
PB9: P7.27 U2.65 | length 1127.7
  Top Layer w8: P7.27@963.11,1936.99 1004.11,1895.99 1004.11,1612.15 1114.48,1501.78 1464.66,1501.78 1538.37,1428.07 U2.65@1538.37,1252.67
PB10: P6.21 U2.29 | length 807.7
  Top Layer w8: U2.29@1664.35,936.31 1664.35,708.01 1906.9,465.46 1906.9,321.37 1948.33,279.95 1948.33,279.84 1962.11,266.06 P6.21@1962.11,251.99
PB11: P6.22 U2.30 | length 701.1
  Top Layer w8: U2.30@1680.1,936.31 1680.1,725.18 1787.28,617.99 1962.11,443.17 P6.22@1962.11,351.99
PB12: P7.1 U2.35 | length 3859.6
  Top Layer w8: U2.35@1773.89,968.5 1872.31,968.5 2017.75,823.07 3352.28,823.07 3472.14,942.93 3472.14,1678.18 3309.87,1840.45 2359.64,1840.45 P7.1@2263.11,1936.99
PB13: P7.2 U2.36 | length 3760.2
  Top Layer w8: U2.36@1773.89,984.25 1894.45,984.25 2039.06,839.64 3340.29,839.64 3453.08,952.43 3453.08,1666.1 3313.04,1806.15 2293.95,1806.15 P7.2@2263.11,1836.99
PB14: P7.3 U2.37 | length 3893.6
  Top Layer w8: U2.37@1773.89,1000 1914.75,1000 2058.54,856.21 3327.92,856.21 3436.2,964.49 3436.2,1654.35 3305.17,1785.39 2234.75,1785.39 2212.99,1807.14 2212.99,1876.93 2163.11,1926.82 P7.3@2163.11,1936.99
PB15: P7.4 U2.38 | length 3776.9
  Top Layer w8: U2.38@1773.89,1015.75 1937.34,1015.75 2077.65,875.44 3321.25,875.44 3417.54,971.73 3417.54,1645.89 3296.1,1767.33 2185.84,1767.33 2163.11,1790.06 P7.4@2163.11,1836.99
PC0: P6.4 U2.8 | length 963.4
  Top Layer w8: P6.4@1062.11,351.99 1062.11,780.73 1391.61,1110.24 U2.8@1460.33,1110.24
PC1: P6.5 U2.9 | length 1046.6
  Top Layer w8: P6.5@1162.11,251.99 1109.53,304.57 1109.53,806.94 1397.08,1094.49 U2.9@1460.33,1094.49
PC2: P6.6 U2.10 | length 884.1
  Top Layer w8: P6.6@1162.11,351.99 1162.11,838.31 1402.54,1078.74 U2.10@1460.33,1078.74
PC3: P6.7 U2.11 | length 966.2
  Top Layer w8: P6.7@1262.11,251.99 1210.87,303.23 1210.87,865.85 1408.01,1062.99 U2.11@1460.33,1062.99
PC4: P6.16 U2.24 | length 616
  Top Layer w8: U2.24@1585.61,936.31 1585.61,623.92 1662.11,547.42 P6.16@1662.11,351.99
PC5: P6.17 U2.25 | length 750.9
  Top Layer w8: U2.25@1601.36,936.31 1601.36,647.15 1708.9,539.61 1708.9,305.2 P6.17@1762.11,251.99
PC10: P7.17 U2.54 | length 787.2
  Top Layer w8: P7.17@1463.11,1936.99 1513.6,1886.49 1513.6,1788.09 1711.59,1590.09 U2.54@1711.59,1252.67
PC11: P7.18 U2.55 | length 680.7
  Top Layer w8: P7.18@1463.11,1836.99 1498.6,1801.49 1498.6,1781.87 1695.85,1584.63 U2.55@1695.85,1252.67
PC12: P7.19 U2.56 | length 846.3
  Top Layer w8: P7.19@1363.11,1936.99 1409.89,1890.2 1409.89,1796.99 1439.65,1767.23 1492.03,1767.23 1680.1,1579.16 U2.56@1680.1,1252.67
PC13: P6.1 PC13.1 U2.2 | length 1877.5
  Top Layer w8: P6.1@962.11,251.99 803.78,410.32 803.78,1298.03 888.84,1383.09 PC13.1@1174.94,1383.09 1174.94,1382.69 1352.91,1204.72 U2.2@1460.33,1204.72
PC14: P6.2 R12.1 | length 1035.6
  Top Layer w8: R12.1@891.69,1301.31 891.69,1300.32 877.38,1286.02 876.4,1286.02 823.42,1233.04 823.42,490.67 P6.2@962.11,351.99
PC15: P6.3 R16.1 | length 1047.5
  Top Layer w8: R16.1@884.72,1189.16 R16.1@887.69,1192.13 ; R16.1@891.69,1186.19 891.69,1185.21 845.2,1138.72 845.2,552.88 1010.79,387.29 1010.79,303.31 P6.3@1062.11,251.99
PD2: P7.20 U2.57 | length 759.9
  Top Layer w8: P7.20@1363.11,1836.99 1363.11,1788.18 1402.97,1748.32 1489.73,1748.32 1664.35,1573.7 U2.57@1664.35,1252.67
PD8: P6.23 U2.33 | length 863
  Top Layer w8: U2.33@1727.34,936.31 1727.34,915.4 1735.39,907.35 1759.34,883.41 1827.62,883.41 2016.38,694.65 2016.38,297.72 P6.23@2062.11,251.99
PD9: P6.24 U2.34 | length 758.7
  Top Layer w8: U2.34@1743.09,936.31 1743.09,923.53 1768.21,898.41 1840.33,898.41 2062.11,676.63 P6.24@2062.11,351.99
PE0: P7.28 U2.66 | length 1040.3
  Top Layer w8: P7.28@963.11,1836.99 963.11,1598.71 1075.03,1486.78 1457.75,1486.78 1522.62,1421.92 U2.66@1522.62,1252.67
VBAT: C12.2 D2.1 P11.3 U2.1 | length 2133.5
  Top Layer w8: C12.2@1322.64,1359.72 v2@1322.64,1333.81 ; U2.1@1460.33,1220.47 1426.54,1220.47 ; v2@1322.64,1333.81 1324.4,1332.05 v2@1324.4,1323.34 ; v2@1322.64,1333.81 1322.64,1325.1 v2@1324.4,1323.34 ; v2@1324.4,1323.34 1324.4,1315.33 1419.26,1220.47 1426.54,1220.47 ; v2@1324.4,1323.34 1333.32,1314.42 1333.32,1313.69 1426.54,1220.47
  Top Layer w30: D2.1@111,1444.91 111,1448.26 112.34,1449.6 118.13,1449.6 125.52,1456.99 P11.3@363.11,1456.99 ; C12.2@1322.64,1359.72 1324.27,1358.08 v2(1324.27,1333.81)
  Bottom Layer w30: P11.3@363.11,1456.99 317.49,1456.99 275.09,1499.38 275.09,1609.74 362.55,1697.19 626.14,1697.19 781.52,1541.81 1149.21,1541.81 1324.27,1366.74 v2(1324.27,1333.81)
VDD: C42.2 C49.2 C50.1 D2.2 P10.7 P10.8 P11.5 U2.32 U2.50 U2.68 | length 4101.1
  Top Layer w8: v2@1388.19,1319.36 1389.09,1319.36 1413.31,1295.14 1473.24,1295.14 1491.12,1277.26 ; C42.2@1391.63,1359.72 1391.63,1327.45 1416.73,1302.35 1474.36,1302.35 1491.12,1285.59 1491.12,1277.26 ; U2.68@1491.12,1252.67 1491.12,1277.26 ; U2.32@1711.59,936.31 1711.59,902.97 1730.99,883.58 1752.85,861.72 1768.61,861.72 1780.77,849.56 1780.77,847.06 C50.1@1785.07,842.76 ; U2.50@1773.89,1204.72 1830.56,1204.72 v2@1850.09,1224.26
  Top Layer w30: D2.2@111.42,1354.49 360.61,1354.49 P11.5@363.11,1356.99 ; v2(1388.15,1330.94) 1388.15,1356.41 1391.46,1359.72 C42.2@1391.63,1359.72 ; C50.1@1796.06,832.76 1798.01,830.8 v2(1823.35,830.8)
  Bottom Layer w30: P11.5@363.11,1356.99 298.45,1356.99 215.97,1439.47 215.97,1639.17 325.98,1749.19 429.95,1749.19 ; 454.35,1773.59 429.95,1749.19 ; P10.7@463.11,1936.99 P10.8@463.11,1836.99 463.11,1776.5 ; v2(1388.15,1330.94) 1388.15,1418.76 1388.15,1454.53 ; 1394.66,1418.76 1430.43,1454.53 ; v2(1823.35,830.8) 1855.47,862.93 v2(1855.47,1222.74) 1899.57,1266.84 1899.57,1359.58 1804.62,1454.53 1430.43,1454.53 ; 429.95,1749.19 455.99,1749.19 ; 455.99,1749.19 490.43,1749.19 ; 455.99,1749.19 463.11,1756.3 463.11,1776.5 ; 463.11,1776.5 473.21,1766.4 490.43,1749.19 ; 490.43,1749.19 675.26,1749.19 823.54,1600.9 1241.78,1600.9 1388.15,1454.53 ; 1388.15,1454.53 1430.43,1454.53
VDDA: C13.1 R19.2 U2.13 | length 549
  Top Layer w8: C13.1@1279.44,838.93 1279.44,878.99 ; 1279.44,884.94 1279.44,878.99 ; C13.1@1280.44,840.93 C13.1@1272.27,832.76 1272.27,878.76 1363.9,970.4 ; U2.13@1460.33,1031.5 1425,1031.5 1363.9,970.4 ; 1279.44,878.99 1363.9,963.45 1363.9,970.4
  Top Layer w30: C13.1@1272.27,832.76 R19.2@1339.92,832.76
VIO: C5.2 C45.1 C47.1 C48.1 P11.1 R19.1 S4.1 U2.17 U2.31 U2.51 U2.67 | length 6987.7
  Top Layer w6: U2.51@1773.89,1220.47 1796.47,1220.47 1847.99,1271.99 1847.99,1294.4 v2@1847.9,1294.49
  Top Layer w8: U2.17@1448.58,968.44 1438.79,958.65 1438.79,900.92 1449.92,889.79 v2(1449.92,862.27) C48.1@1449.92,842.76 ; v2(1480.05,1353.38) 1506.87,1326.57 U2.67@1506.87,1252.67 ; U2.31@1695.85,936.31 1695.85,877.21 1713.61,859.44 v2(1713.61,856.74) ; v2@1847.9,1294.49 C45.1@1881.48,1294.49
  Top Layer w30: v2(1320,740) v2@1331.29,740 ; R19.1@1339.92,772.13 1340.91,772.13 1344.21,768.82 v2@1344.21,752.92 ; C47.1@1461.63,1359.72 1464.94,1356.41 1477.02,1356.41 v2(1480.05,1353.38) ; v2(1713.61,856.74) 1713.61,851.25 1721.77,843.1 1721.77,836.06 1725.07,832.76 C5.2@1726.06,832.76 ; v2(1847.99,1295.48) 1872.75,1295.48 1876.72,1299.44 1881.57,1294.59 C45.1@1881.48,1294.49 ; v2(2302.3,148.41) 2343.62,148.41 v2@2344.11,148.9 ; v2(2342.37,148.1) 2416.25,74.22 2941.6,74.22 3042,174.61 S4.1@3042,215.99 ; v2@1331.29,740 v2@1344.21,752.92 ; v2@1331.29,740 1346.65,740 v2(1351.9,745.24) v2@1344.21,752.92
  Bottom Layer w30: P11.1@363.11,1556.99 366.09,1559.97 366.09,1603.81 406.76,1644.48 559.91,1644.48 722.41,1481.97 1100.84,1481.97 1246.97,1335.84 1298.25,1284.56 1450.37,1284.56 1480.05,1314.24 v2(1480.05,1353.38) 1515.17,1388.5 1797.95,1388.5 1847.99,1338.45 v2(1847.99,1295.48) 1847.99,1283.88 1798.09,1233.97 1798.09,907.14 1747.68,856.74 v2(1713.61,856.74) 1456.06,856.74 1450.52,862.27 v2(1449.92,862.27) 1449.92,851.92 1338,740 v2(1320,740) 821.79,740 716.29,634.5 716.29,281.15 849.35,148.1 v2@2302.62,148.1 ; v2(2302.3,148.41) v2@2302.62,148.1 ; v2(2342.37,148.1) v2@2302.62,148.1
X32KI: C9.2 R12.2 U2.3 Y2.1 | length 610.1
  Top Layer w8: R12.2@952.32,1301.31 963.63,1312.61 963.63,1336.28 974.2,1346.86 1063.54,1346.86 1078.32,1332.08 C9.2@1078.32,1301.31 ; C9.2@1084.89,1283.69 Y2.1@1174.48,1283.69 ; Y2.1@1174.48,1283.16 1234.05,1283.16 1328.23,1188.98 U2.3@1460.33,1188.98
X32KO: C10.2 R16.2 U2.4 Y2.2 | length 558.3
  Top Layer w8: R16.2@948.32,1185.21 962.63,1170.9 963.61,1170.9 987.73,1146.78 1039.52,1146.78 1063.64,1170.9 1064.01,1170.9 1078.32,1185.21 C10.2@1078.32,1186.19 1088.07,1195.94 1169.81,1195.94 1174.8,1190.95 1285.85,1190.95 1303.56,1173.23 U2.4@1460.33,1173.23
XI: C7.2 U2.5 Y1.1 | length 457.1
  Top Layer w8: C7.2@1029.83,1095.74 1031.09,1094.48 1115.58,1094.48 1159.23,1138.13 1272.38,1138.13 1291.73,1157.48 U2.5@1460.33,1157.48
XO: C8.2 U2.6 Y1.3 | length 502.4
  Top Layer w8: C8.2@1029.83,1000.46 1029.83,999.48 1044.14,985.17 1045.13,985.17 1065.07,965.23 1155.62,965.23 1172.73,982.34 Y1.3@1172.73,986.28 ; Y1.3@1190.39,1003.93 1190.39,1007.87 1208.04,1025.52 1209.38,1025.52 1325.59,1141.73 U2.6@1460.33,1141.73 ; Y1.3@1203.39,996.93 Y1.3@1203.39,1000.87
pads on no net: P2. P2.7 P14.A8 P14.B8 P15.A8 P15.B8 S1.0 S1.3 U1.

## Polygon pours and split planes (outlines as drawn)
GND on Top Layer "GND" (hatched 90Degree grid 8 track 8, remove dead copper, pour order 0): 0,3070.87 0,0 3543.31,0 3543.31,3070.87
GND on Bottom Layer "GND" (hatched 90Degree grid 8 track 8, remove dead copper, pour order 1): 0,3070.87 0,0 3543.31,0 3543.31,3070.87

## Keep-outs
Keep-Out Layer:
  the board outline again, w15

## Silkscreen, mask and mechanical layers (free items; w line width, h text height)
Top Overlay:
  lines w10: 244.17,531.19 244.17,1142.89
  text "ON" at 296.8,2694.87 h40
  text "OFF" at 478.68,2694.87 h40
  text "SWCK" at 741.59,2143.33 h35 r270
  text "PA14" at 1538.83,2135.33 h35 r270
  text "PC12" at 1338.81,2133.66 h35 r270
  text "PC10" at 1438.82,2133.66 h35 r270
  text "PA12" at 1638.83,2133.66 h35 r270
  text "PA10" at 1738.84,2133.66 h35 r270
  text "PB14" at 2138.88,2131.66 h35 r270
  text "PB12" at 2238.89,2130 h35 r270
  text "SWIO" at 641.72,2119.17 h35 r270
  text "PA8" at 1838.85,2108 h35 r270
  text "PC8" at 1938.86,2108 h35 r270
  text "PC6" at 2038.87,2106.34 h35 r270
  text "PB7" at 1038.78,2104.34 h35 r270
  text "PB5" at 1138.79,2104.34 h35 r270
  text "PB3" at 1238.8,2104.34 h35 r270
  text "GND" at 541.85,2103 h35 r270
  text "PB9" at 938.77,2102.67 h35 r270
  text "VDD" at 441.98,2099.34 h35 r270
  text "5V" at 342.11,2071.51 h35 r270
  text "CH32V30xW-R0-1v0" at 2729.47,2059.24 h40
  text "5V" at 337.89,1778.86 h35 r270
  text "VDD" at 438.81,1778.86 h35 r270
  text "GND" at 539.74,1778.86 h35 r270
  text "RXD" at 640.66,1778.86 h35 r270
  text "TXD" at 741.59,1778.86 h35 r270
  text "PE0" at 938.77,1769.36 h35 r270
  text "PB8" at 1038.78,1769.36 h35 r270
  text "PB6" at 1138.79,1769.36 h35 r270
  text "PB4" at 1238.8,1769.36 h35 r270
  text "PD2" at 1338.81,1769.36 h35 r270
  text "PC11" at 1438.82,1769.36 h35 r270
  text "PA15" at 1538.83,1769.36 h35 r270
  text "PA13" at 1638.83,1769.36 h35 r270
  text "PA11" at 1738.84,1769.36 h35 r270
  text "PA9" at 1838.85,1769.36 h35 r270
  text "PC9" at 1938.86,1769.36 h35 r270
  text "PC7" at 2038.87,1769.36 h35 r270
  text "PB15" at 2138.88,1769.36 h35 r270
  text "PB13" at 2238.89,1769.36 h35 r270
  text "VIO" at 214.94,1534.36 h35
  text "3V3" at 538.42,1534.36 h35
  text "VBAT" at 159.62,1433.26 h35
  text "3V3" at 538.42,1433.26 h35
  text "VDD" at 194.45,1332.16 h35
  text "3V3" at 538.42,1332.16 h35
  text "GND" at 192.27,1163.19 h35
  text "GND" at 536.58,1163.19 h35
  text "GND" at 536.58,1062.93 h35
  text "5V" at 552.33,962.66 h35
  text "ELED2" at 3280.82,948.94 h35 r270
  text "ELED1" at 3181.68,933.94 h35 r270
  text "GND" at 3079.53,904.95 h35 r270
  text "5V" at 552.33,862.4 h35
  text "5V" at 552.33,762.13 h35
  text "3V3" at 538.42,661.87 h35
  text "LED1" at 3079.53,582 h35 r270
  text "LED2" at 3181.68,582 h35 r270
  text "KEY" at 3280.82,582 h35 r270
  text "BOOT1" at 2137.67,572.84 h35 r270
  text "3V3" at 538.42,561.6 h35
  text "PC14" at 937.36,552.84 h35 r270
  text "PB11" at 1937.62,532.51 h35 r270
  text "PA4" at 1437.49,527.18 h35 r270
  text "PC4" at 1637.54,527.18 h35 r270
  text "PC0" at 1037.38,525.52 h35 r270
  text "PC2" at 1137.41,525.52 h35 r270
  text "PA0" at 1237.43,525.52 h35 r270
  text "PA2" at 1337.46,525.52 h35 r270
  text "GND" at 2237.7,525.52 h35 r270
  text "PA6" at 1537.51,523.85 h35 r270
  text "PB0" at 1737.57,521.85 h35 r270
  text "PB2" at 1837.59,521.85 h35 r270
  text "PD9" at 2037.64,520.18 h35 r270
  text "GND" at 192.27,461.34 h35
  text "3V3" at 538.42,461.34 h35
  text "PC13" at 937.36,186.37 h35 r270
  text "PC15" at 1037.38,186.37 h35 r270
  text "PC1" at 1137.41,186.37 h35 r270
  text "PC3" at 1237.43,186.37 h35 r270
  text "PA1" at 1337.46,186.37 h35 r270
  text "PA3" at 1437.49,186.37 h35 r270
  text "PA5" at 1537.51,186.37 h35 r270
  text "PA7" at 1637.54,186.37 h35 r270
  text "PC5" at 1737.56,186.37 h35 r270
  text "PB1" at 1837.59,186.37 h35 r270
  text "PB10" at 1937.62,186.37 h35 r270
  text "PD8" at 2037.64,186.37 h35 r270
  text "BOOT0" at 2137.67,186.37 h35 r270
  text "GND" at 2237.7,186.37 h35 r270
Mechanical 1:
  the board outline again, w10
